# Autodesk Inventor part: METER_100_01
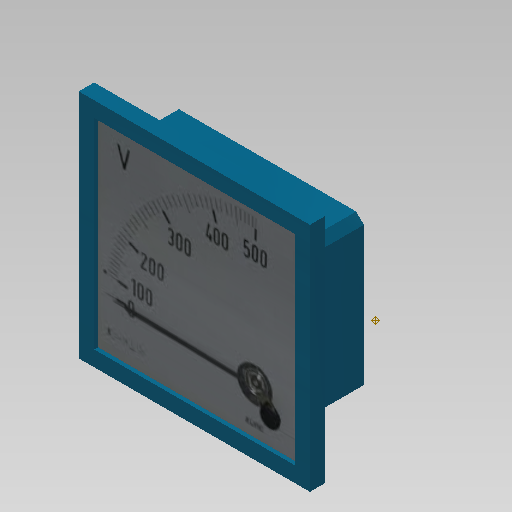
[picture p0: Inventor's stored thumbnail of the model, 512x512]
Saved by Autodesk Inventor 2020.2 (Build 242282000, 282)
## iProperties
Manager: www.cadconsulting.pl
Company: Fabian Stasiak CAD Consulting
GlobalPropertyList: <PropertyList/>
Created: 2014-09
Part Number: METER_100_01
Material: Ogólny
Document SubType Name: Modeling
Designer: F.Stasiak
Density: 1 g/cm^3
Appearance: Ciemnobłękitna
Catalog Web Link: www.expertbooks.pl
Author: F.Stasiak
Subject: Zbiór ćwiczeń. Autodesk Inventor 2020. Kurs Professional
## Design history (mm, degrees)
sketch "Szkic1"
  geometry: L1 (-25, -20)-(25, -20); L2 (25, -20)-(25, 20); L3 (25, 20)-(-25, 20); L4 (-25, 20)-(-25, -20); L5 (-25, -20)-(25, 20); L6 (25, -20)-(-25, 20); 1 further point
  constraints: 12 end point, 2 midpoint, 2 parallel, 1 horizontal, 1 perpendicular
  dimensions: "d0" = 50 distance of L2.end L3.end; "d1" = 40 distance of L3.end L1.start
extrude "Wyciągnięcie proste1" new body sketch "Szkic1" distance "d2" = 15; taper "d3" = 0 deg
sketch "Szkic2"
  geometry: L1 (-30, 30)-(30, 30); L2 (30, 30)-(30, -30); L3 (30, -30)-(-30, -30); L4 (-30, -30)-(-30, 30); L5 (-30, 30)-(30, -30); L6 (30, 30)-(-30, -30); 1 further point
  constraints: 12 end point, 2 midpoint, 2 parallel, 1 horizontal, 1 perpendicular
  dimensions: "d4" = 60 distance of L2.end L3.end; "d5" = 60 distance of L1.end L2.end
extrude "Wyciągnięcie proste2" join sketch "Szkic2" distance "d6" = 4; taper "d7" = 0 deg
sketch "Szkic3"
  geometry: L1 (30, 30)-(-30, 30) reference; L2 (-30, 30)-(-30, -30) reference; L3 (-30, -30)-(30, -30) reference; L4 (30, -30)-(30, 30) reference; L5 (-26, 26)-(26, 26); L6 (26, 26)-(26, -26); L7 (26, -26)-(-26, -26); L8 (-26, -26)-(-26, 26); 1 further point
  constraints: 8 end point, 3 other
  dimensions: "d8" = 4 distance between parallel lines of L1 L5
extrude "Wyciągnięcie proste3" cut sketch "Szkic3" distance "d9" = 1; taper "d10" = 0 deg
derived "Z_02.ipt"
feature "Przesuń bryłę2"
chamfer "Faza1" distance "d20" = 2; stored, may be unused: second distance "d21" = 2, angle "d22" = 45 deg
feature "Utwórz kombinację1"
  node "Bryła2"
sketch "Szkic4"
  geometry: C1 r 1 at (2, -2.5) reference
node "M1"
sketch "Szkic5"
  geometry: C1 r 1 at (6, -2.5) reference
node "M2"
sketch "Szkic6"
  geometry: L1 (-26.778, 26)-(26.778, 26); L2 (26.778, 26)-(26.778, -26); L3 (26.778, -26)-(-26.778, -26); L4 (-26.778, -26)-(-26.778, 26); L5 (-26, 26)-(26, 26) reference; L6 (-26, -26)-(-26, 26) reference; L7 (26, -26)-(-26, -26) reference; L8 (26, 26)-(26, -26) reference; L9 (-26, 26)-(26, 26) reference; L10 (26, -26)-(-26, -26) reference; 3 further points; 1 other entity
  constraints: 4 midpoint, 2 other
feature "Pokrycie bitmapą1" sketch "Szkic6"
node "Płaszczyzna konstrukcyjna1"
node "Płaszczyzna konstrukcyjna2"
node "Płaszczyzna konstrukcyjna4"
node "Płaszczyzna konstrukcyjna3"
node "Punkt konstrukcyjny3"
node "Punkt konstrukcyjny4"
node "Bryła1"
node "Pętla rzutowana1"
feature "Bryła1::Z_02.ipt" dims "d11" = 10
tag "Bryła wyprowadzona1"
node "Obraz1"
node "Pętla rzutowana2"
other parameters: "d16" = 90 deg, "d17" = 15, "d18" = -15, "d19" = 0, "d26" = 3, "d27" = 5
